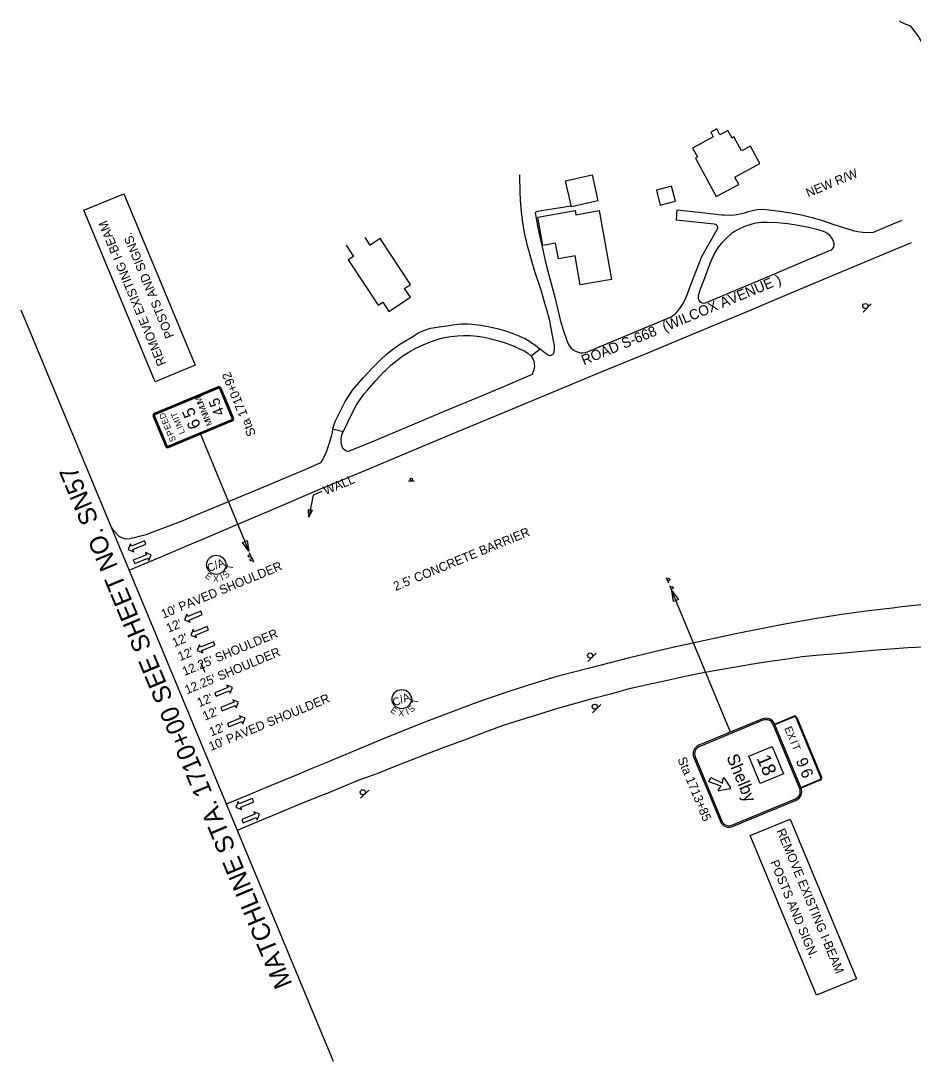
# Model space of a CAD drawing. Extents: x 1817507 to 1819117, y 1191678 to 1192982.
# Drawn here: x 1817507 to 1818204, y 1191678 to 1192491 of the extents above; entities that cross this region are included whole.
import ezdxf

# ---------------------------------------------------------------- set-up
doc = ezdxf.new("R2010")
doc.units = 0
for name, color, linetype in [('RD_EX_Bldg', 7, 'Continuous'), ('RD_EX_Road', 7, 'Continuous'), ('RD_HC_Data_Tic', 7, 'Continuous'), ('RD_PD_Final_LnLine', 7, 'Continuous'), ('RD_PD_Final_TX', 7, 'Continuous'), ('RD_PD_RW_TX', 7, 'Continuous'), ('RD_SHT_MatchLine', 7, 'Continuous'), ('RD_SHT_TX', 7, 'Continuous'), ('RD_Sketch8', 7, 'Continuous'), ('RD_TX_RoadID', 7, 'Continuous'), ('SN_P_Signs', 7, 'Continuous'), ('TERMINATOR', 7, 'Continuous')]:
    doc.layers.add(name, color=color, linetype=linetype)

# ---------------------------------------------------------------- blocks, each defined once
blk = doc.blocks.new('SARRW2')
at = {"layer": 'RD_PD_Final_LnLine'}
blk.add_lwpolyline([(-12, 1.2), (-12, -1.2), (-2.83, -1.2), (-2.83, -2.83), (0, 0), (-2.83, 2.83), (-2.83, 1.2)], close=True, dxfattribs=at)

msp = doc.modelspace()

# ---------------------------------------------------------------- linework, layer by layer
at = {"layer": 'RD_EX_Bldg'}
for points in [[(1818031.47, 1192391.37), (1818035.22, 1192384.42), (1818033.69, 1192383.6), (1818049.94, 1192353.45), (1818067.63, 1192362.98), (1818064.54, 1192368.72), (1818083.98, 1192379.2), (1818076.62, 1192392.85), (1818069.66, 1192389.1), (1818063.78, 1192400.02), (1818062.29, 1192399.22), (1818059.13, 1192405.06), (1818052.88, 1192401.69), (1818050.41, 1192406.26), (1818045.67, 1192403.7), (1818047.63, 1192400.08), (1818031.47, 1192391.37)], [(1817932.31, 1192365.67), (1817952.95, 1192370.38), (1817957.57, 1192350.16), (1817936.93, 1192345.45), (1817932.31, 1192365.67)], [(1818003.23, 1192358.55), (1818006.23, 1192346.88), (1818018.11, 1192349.93), (1818015.11, 1192361.6), (1818003.23, 1192358.55)], [(1817914.48, 1192315.22), (1817910.53, 1192337.34), (1817939.79, 1192342.58), (1817940.38, 1192339.28), (1817958.52, 1192342.52), (1817968.11, 1192288.87), (1817943.81, 1192284.53), (1817939.74, 1192307.29), (1817926.67, 1192304.95), (1817924.51, 1192317.01), (1817914.48, 1192315.22)], [(1817760.94, 1192315.48), (1817766.66, 1192306.82), (1817762.48, 1192304.05), (1817785.91, 1192268.6), (1817789.6, 1192271.04), (1817794.37, 1192263.81), (1817811.08, 1192274.85), (1817806.49, 1192281.79), (1817811.23, 1192284.92), (1817787.51, 1192320.81), (1817779.61, 1192315.58), (1817775.7, 1192321.49)]]:
    msp.add_lwpolyline(points, dxfattribs=at)
at = {"layer": 'RD_EX_Road'}
for points in [[(1818261.58, 1192366.73), (1818262.42, 1192368.15), (1818263.13, 1192369.69), (1818263.78, 1192371.95), (1818264.05, 1192374.28), (1818263.92, 1192376.63), (1818263.72, 1192377.76), (1818263.24, 1192380.13), (1818262.38, 1192382.4), (1818261.87, 1192383.37), (1818257.12, 1192392.2), (1818250.7, 1192404.08), (1818244.61, 1192414.31), (1818236, 1192429.02), (1818230.42, 1192439.59), (1818223.55, 1192452.27), (1818216.46, 1192464.6), (1818209.02, 1192476.73), (1818208.32, 1192477.83), (1818201.84, 1192486.47), (1818198.24, 1192487.72), (1818194.24, 1192489.73), (1818193.11, 1192490.73)], [(1817896.23, 1192370.43), (1817896.28, 1192369.33), (1817896.46, 1192357.47), (1817896.78, 1192350.57), (1817897.55, 1192341.7), (1817898.7, 1192332.87), (1817900.25, 1192324.1), (1817902.18, 1192315.4), (1817908.13, 1192295.38), (1817913.13, 1192279.94), (1817915.6, 1192271.29), (1817917.19, 1192266.04), (1817919.37, 1192257.72), (1817921.17, 1192249.31), (1817922.92, 1192239.6), (1817923.29, 1192237.51), (1817923.44, 1192234.75), (1817923.19, 1192231.99), (1817922.95, 1192231.12), (1817922.33, 1192230.2), (1817921.43, 1192229.55), (1817920.36, 1192229.25), (1817919.25, 1192229.35), (1817918.24, 1192229.82), (1817916.84, 1192230.92), (1817916.39, 1192231.3), (1817912.55, 1192234.38), (1817905.5, 1192228.81), (1817906.62, 1192227.09), (1817907.44, 1192225.12), (1817907.88, 1192223.03), (1817907.94, 1192220.9), (1817907.6, 1192218.8), (1817907.46, 1192218.33), (1817906.82, 1192216.07), (1817906.32, 1192214.46), (1817883.9, 1192205.01), (1817863.19, 1192196.39), (1817838, 1192185.86), (1817814.07, 1192175.86), (1817799.28, 1192169.66), (1817778.86, 1192161.04), (1817762.56, 1192154.46), (1817761.13, 1192154.8), (1817759.85, 1192155.52), (1817758.79, 1192156.54), (1817758.2, 1192157.48), (1817757.41, 1192159.97), (1817757, 1192162.55), (1817756.94, 1192163.92), (1817757.37, 1192166.53), (1817758.19, 1192169.05), (1817758.52, 1192169.78), (1817758.53, 1192169.81), (1817750.31, 1192171.98), (1817749.95, 1192169.61), (1817749.27, 1192166.3), (1817747.45, 1192160.14), (1817745.6, 1192154.79), (1817744.85, 1192152.82), (1817743.11, 1192149.09), (1817741.02, 1192145.54), (1817728.69, 1192140.25), (1817693.3, 1192125.42), (1817658.23, 1192110.83), (1817636.34, 1192101.67)], [(1817936.79, 1192346.06), (1817910.08, 1192341.77), (1817909.03, 1192341.34), (1817908.66, 1192340.74), (1817910.31, 1192330.69), (1817912.34, 1192320.71), (1817914.76, 1192310.81), (1817915.18, 1192309.25), (1817917.66, 1192298.06), (1817923.93, 1192274.91), (1817928.11, 1192257.27), (1817930.36, 1192249.53), (1817932.99, 1192241.91), (1817934.1, 1192239.03), (1817935.15, 1192237.1), (1817936.53, 1192235.39), (1817938.19, 1192233.95), (1817940.08, 1192232.83), (1817942.15, 1192232.07), (1817942.31, 1192232.03), (1817944.07, 1192231.52), (1817945.9, 1192231.41), (1817947.71, 1192231.69), (1817948.12, 1192231.81), (1817976.76, 1192243.75), (1818014.73, 1192259.52), (1818015.59, 1192260.09), (1818018.04, 1192262.16), (1818018.91, 1192263.07), (1818021.41, 1192266.06), (1818023.6, 1192269.29), (1818025.45, 1192272.72), (1818026.95, 1192276.32), (1818032.1, 1192290.13), (1818038.72, 1192306.82), (1818040.94, 1192310.77), (1818050.79, 1192327.78), (1818051.1, 1192328.46), (1818051.2, 1192329.49), (1818050.91, 1192330.48), (1818050.27, 1192331.29), (1818049.38, 1192331.8), (1818048.36, 1192331.95), (1818041, 1192332.7), (1818018.84, 1192334.98), (1818019.57, 1192343.07), (1818041.03, 1192340.88), (1818054.43, 1192339.29), (1818055.77, 1192339.16), (1818060.12, 1192339.03), (1818064.46, 1192339.29), (1818068.76, 1192339.94), (1818072.98, 1192340.97), (1818074.89, 1192341.72), (1818078.4, 1192342.75), (1818081.99, 1192343.4), (1818085.63, 1192343.66), (1818089.28, 1192343.53), (1818092.89, 1192343), (1818099.89, 1192342.23), (1818108.29, 1192340.93), (1818116.62, 1192339.25), (1818124.86, 1192337.19), (1818133, 1192334.74), (1818141.01, 1192331.92), (1818156.15, 1192327.21), (1818156.46, 1192327.12), (1818160.46, 1192326.18), (1818164.53, 1192325.63), (1818168.64, 1192325.47), (1818172.74, 1192325.7), (1818188.21, 1192332.29), (1818195.06, 1192335.13)], [(1818139.29, 1192311.67), (1818140.18, 1192312), (1818141, 1192312.85), (1818141.72, 1192314.11), (1818142.07, 1192315.52), (1818142.04, 1192316.97), (1818141.62, 1192318.36), (1818141.12, 1192319.61), (1818140.01, 1192321.51), (1818138.59, 1192323.19), (1818136.89, 1192324.59), (1818134.96, 1192325.66), (1818132.88, 1192326.38), (1818128.54, 1192327.71), (1818122.05, 1192329.36), (1818121.9, 1192329.4), (1818113.98, 1192330.95), (1818105.98, 1192332.12), (1818097.94, 1192332.9), (1818089.87, 1192333.28), (1818089.48, 1192333.29), (1818085.28, 1192333.16), (1818081.12, 1192332.63), (1818077.02, 1192331.71), (1818073.03, 1192330.41), (1818071.64, 1192329.92), (1818068.14, 1192328.4), (1818064.81, 1192326.52), (1818061.7, 1192324.31), (1818058.82, 1192321.79), (1818056.94, 1192320.03), (1818053.86, 1192316.73), (1818051.07, 1192313.17), (1818048.61, 1192309.38), (1818045.22, 1192301.7), (1818040.68, 1192289.88), (1818037.1, 1192280.33), (1818035.94, 1192275.95), (1818035.97, 1192273.84), (1818036.22, 1192272.94), (1818036.87, 1192271.85), (1818037.82, 1192271.01), (1818038.98, 1192270.5), (1818040.24, 1192270.37), (1818041.48, 1192270.63), (1818060.96, 1192278.7), (1818086.3, 1192289.39), (1818121.84, 1192304.39), (1818139.29, 1192311.67)], [(1817645.01, 1192084.41), (1817648.4, 1192085.86), (1817658.77, 1192090.29), (1817674.63, 1192096.91), (1817701.6, 1192108.51), (1817736.86, 1192123.57), (1817778.21, 1192140.68), (1817814.58, 1192155.92), (1817849.51, 1192170.5), (1817887.79, 1192186.58), (1817932.79, 1192205.24), (1817958.22, 1192215.86), (1817997.72, 1192232.05), (1818037.55, 1192248.7), (1818075.33, 1192264.29), (1818110.36, 1192279.19), (1818145.64, 1192293.97), (1818180.68, 1192308.65), (1818202.37, 1192317.6)], [(1817750.31, 1192171.98), (1817752.72, 1192178.32), (1817755.44, 1192184.17), (1817757.88, 1192188.72), (1817760.25, 1192193.43), (1817762.97, 1192197.95), (1817766.02, 1192202.26), (1817767.8, 1192204.49), (1817774.48, 1192212.31), (1817781.44, 1192219.86), (1817787.41, 1192225.9), (1817792.09, 1192230.14), (1817797.02, 1192234.07), (1817802.19, 1192237.69), (1817807.26, 1192240.79), (1817811.82, 1192243.51), (1817813.8, 1192244.8), (1817816.92, 1192246.8), (1817820.24, 1192248.46), (1817823.72, 1192249.76), (1817827.09, 1192250.63), (1817831.71, 1192251.43), (1817841.21, 1192252.87), (1817846, 1192253.66), (1817850.84, 1192254.06), (1817855.7, 1192254.07), (1817859.38, 1192253.81), (1817866.29, 1192252.99), (1817873.14, 1192251.78), (1817879.91, 1192250.19), (1817885.32, 1192248.62), (1817890.66, 1192246.92), (1817895.87, 1192244.84), (1817900.91, 1192242.41), (1817904.25, 1192240.55), (1817910.44, 1192236.08), (1817912.55, 1192234.38)], [(1817758.53, 1192169.81), (1817762.26, 1192177.37), (1817766.66, 1192186.39), (1817769.06, 1192190.88), (1817771.81, 1192195.17), (1817774.88, 1192199.24), (1817777.62, 1192202.38), (1817783.91, 1192209.62), (1817790.5, 1192216.6), (1817791.64, 1192217.75), (1817795.93, 1192221.83), (1817800.48, 1192225.62), (1817805.28, 1192229.09), (1817809.99, 1192232.06), (1817815.44, 1192235.12), (1817821.07, 1192237.84), (1817826.87, 1192240.19), (1817832.7, 1192242.15), (1817837.71, 1192243.44), (1817842.8, 1192244.34), (1817847.94, 1192244.85), (1817852.69, 1192244.97), (1817858.04, 1192244.91), (1817863.38, 1192244.45), (1817868.67, 1192243.61), (1817873.88, 1192242.38), (1817874.45, 1192242.22), (1817880.25, 1192240.84), (1817885.94, 1192239.09), (1817891.5, 1192236.97), (1817896.92, 1192234.48), (1817897.02, 1192234.43), (1817900.01, 1192232.94), (1817902.79, 1192231.12), (1817905.5, 1192228.81)], [(1817636.34, 1192101.67), (1817633.34, 1192100.42), (1817605.7, 1192089.83)], [(1817577.66, 1192094.8), (1817578.53, 1192093.71), (1817583.41, 1192088.25), (1817585.41, 1192087.23), (1817587.55, 1192086.57), (1817589.78, 1192086.3), (1817592.02, 1192086.42), (1817594.2, 1192086.93), (1817594.72, 1192087.11), (1817600.51, 1192088.51), (1817605.7, 1192089.83)], [(1817591.4, 1192061.72), (1817599.97, 1192065.4), (1817618.26, 1192073.01), (1817633.33, 1192079.43), (1817645.01, 1192084.41)], [(1818214.62, 1192035.23), (1818192.87, 1192032.88), (1818187.62, 1192032.26), (1818166.84, 1192029.75), (1818146.11, 1192026.86), (1818125.44, 1192023.58), (1818104.84, 1192019.9), (1818096.74, 1192018.35), (1818065.31, 1192012.08), (1818033.97, 1192005.43), (1818013.74, 1192000.92), (1817982.27, 1191993.35), (1817950.9, 1191985.4), (1817925.55, 1191978.67), (1817907.52, 1191973.39), (1817889.61, 1191967.72), (1817871.81, 1191961.69), (1817860.95, 1191957.8), (1817838.7, 1191949.51), (1817820.42, 1191942.39), (1817789.45, 1191929.77), (1817743.27, 1191910.63), (1817734.2, 1191906.85)], [(1817744.22, 1191886.93), (1817753.55, 1191890.71), (1817771.02, 1191898.04), (1817785.23, 1191902.96), (1817799.2, 1191908.67), (1817813.22, 1191914.27), (1817827.35, 1191919.66), (1817841.22, 1191924.95), (1817855.35, 1191930.19), (1817869.68, 1191935.48), (1817883.86, 1191940.77), (1817897.94, 1191945.19), (1817912.11, 1191949.66), (1817926.34, 1191954.08), (1817940.27, 1191957.98), (1817954.24, 1191961.89), (1817968.31, 1191965.64), (1817982.24, 1191969.34), (1817996.05, 1191972.52), (1818009.62, 1191975.5), (1818023.33, 1191978.58), (1818036.95, 1191981.31), (1818049.89, 1191983.77), (1818063.61, 1191986.13), (1818077.07, 1191988.34), (1818089.91, 1191990.6), (1818103.52, 1191992.45), (1818116.98, 1191994.3), (1818130.7, 1191995.64), (1818144.42, 1191996.87), (1818158.23, 1191998.16), (1818172.16, 1191999.23), (1818185.77, 1192000.42), (1818199.49, 1192001.44), (1818212.84, 1192002.06)], [(1817734.2, 1191906.85), (1817722.75, 1191902.08), (1817697.85, 1191891.9), (1817683.04, 1191885.66), (1817667.28, 1191879.14)], [(1817744.22, 1191886.93), (1817738.67, 1191884.67), (1817724.73, 1191879), (1817711.35, 1191873.31), (1817692.91, 1191865.73), (1817675.81, 1191858.62)]]:
    msp.add_lwpolyline(points, dxfattribs=at)
at = {"layer": 'RD_HC_Data_Tic'}
msp.add_line((1817650.9, 1191981.81), (1817647.83, 1191989.2), dxfattribs=at)
at = {"layer": 'RD_PD_Final_TX'}
for p, q in [((1817735.14, 1192120.35), (1817731.88, 1192103.11)), ((1817742.02, 1192123.21), (1817735.14, 1192120.35))]:
    msp.add_line(p, q, dxfattribs=at)
at = {"layer": 'RD_SHT_MatchLine'}
msp.add_line((1817506.85, 1192265.17), (1817750.69, 1191678.44), dxfattribs=at)
at = {"layer": 'RD_Sketch8'}
for centre in [(1817659.5, 1192066), (1817804.29, 1191961.12)]:
    msp.add_circle(centre, 7.5, dxfattribs=at)
at = {"layer": 'SN_P_Signs'}
for p, q in [((1817556.2, 1192342.81), (1817587.24, 1192355.71)), ((1817587.24, 1192355.71), (1817642.9, 1192221.79)), ((1817611.85, 1192208.89), (1817556.2, 1192342.81)), ((1818164.65, 1192263.37), (1818171.01, 1192269.73)), ((1817642.9, 1192221.79), (1817611.85, 1192208.89)), ((1817660.95, 1192204.92), (1817611.08, 1192184.19)), ((1817672.97, 1192180.68), (1817663.3, 1192203.95)), ((1817610.11, 1192181.84), (1817619.78, 1192158.57)), ((1817622.13, 1192157.6), (1817672, 1192178.32)), ((1817647.07, 1192167.96), (1817684.98, 1192076.74)), ((1817809.6, 1192131.67), (1817814.1, 1192131.67)), ((1817687.18, 1192071.18), (1817685.45, 1192075.34)), ((1817688.79, 1192068.15), (1817687.06, 1192072.3)), ((1818010.82, 1192056.14), (1818012.57, 1192051.99)), ((1818013.57, 1192049.8), (1818015.32, 1192045.66)), ((1818061.15, 1191935.38), (1818015.32, 1192045.66)), ((1817949.77, 1191990.53), (1817956.13, 1191996.89)), ((1817953.35, 1191950.54), (1817959.72, 1191956.9)), ((1818086.47, 1191944.6), (1818036.75, 1191923.94)), ((1818075.48, 1191916.62), (1818093.66, 1191924.17)), ((1818084.33, 1191895.31), (1818075.48, 1191916.62)), ((1818102.52, 1191902.87), (1818084.33, 1191895.31)), ((1817772.19, 1191883.81), (1817778.56, 1191890.17)), ((1818062.2, 1191862.7), (1818111.92, 1191883.36)), ((1818076.53, 1191854.55), (1818107.58, 1191867.45)), ((1818107.58, 1191867.45), (1818159.39, 1191742.77)), ((1818128.35, 1191729.87), (1818076.53, 1191854.55)), ((1818159.39, 1191742.77), (1818128.35, 1191729.87))]:
    msp.add_line(p, q, dxfattribs=at)
for points in [[(1817661.12, 1192204.5), (1817611.25, 1192183.78)], [(1817661.41, 1192203.81), (1817611.54, 1192183.09)], [(1817671.86, 1192180.21), (1817662.19, 1192203.49)], [(1817672.55, 1192180.5), (1817662.88, 1192203.77)], [(1817610.53, 1192182.01), (1817620.2, 1192158.74)], [(1817611.22, 1192182.3), (1817620.89, 1192159.03)], [(1817621.67, 1192158.71), (1817671.54, 1192179.43)], [(1817621.96, 1192158.01), (1817671.83, 1192178.74)], [(1818086, 1191945.71), (1818036.29, 1191925.05)], [(1818115.15, 1191891.2), (1818094.31, 1191941.36)], [(1818116.26, 1191891.66), (1818095.42, 1191941.82)], [(1818110.73, 1191947.19), (1818095.77, 1191940.97), (1818095.54, 1191941.53), (1818110.5, 1191947.74)], [(1818131.64, 1191900), (1818112.3, 1191946.54)], [(1818112.85, 1191946.77), (1818132.19, 1191900.23)], [(1818093.66, 1191924.17), (1818102.52, 1191902.87)], [(1818032.4, 1191915.64), (1818053.25, 1191865.48)], [(1818033.51, 1191916.1), (1818054.36, 1191865.94)], [(1818044.26, 1191896.49), (1818045.63, 1191899.82), (1818054.75, 1191895.57)], [(1818053.72, 1191893.07), (1818044.26, 1191896.49)], [(1818051.54, 1191890.11), (1818053.72, 1191893.07)], [(1818054.75, 1191895.57), (1818055.29, 1191899.2)], [(1818056.11, 1191899.39), (1818061.13, 1191891.88)], [(1818116.03, 1191892.22), (1818130.99, 1191898.43)], [(1818131.22, 1191897.88), (1818116.26, 1191891.66), (1818116.03, 1191892.22)], [(1818060.84, 1191891.19), (1818051.99, 1191889.41)], [(1818062.66, 1191861.59), (1818112.38, 1191882.25)]]:
    msp.add_lwpolyline(points, dxfattribs=at)
for points in [[(1817683.72, 1192085.1), (1817684.98, 1192076.74), (1817679.93, 1192083.53)], [(1818016.71, 1192037.32), (1818015.36, 1192045.67), (1818020.48, 1192038.94)]]:
    msp.add_lwpolyline(points, close=True, dxfattribs=at)
for centre, radius in [((1818166.41, 1192267.99), 2), ((1817811.85, 1192132.68), 1), ((1817685.38, 1192072.88), 1), ((1817686.98, 1192069.84), 1), ((1818012.63, 1192054.45), 1), ((1818015.38, 1192048.11), 1), ((1817951.53, 1191995.15), 2), ((1817955.12, 1191955.16), 2), ((1817773.96, 1191888.43), 2)]:
    msp.add_circle(centre, radius, dxfattribs=at)
for centre, radius, start, end in [((1817661.64, 1192203.25), 1.8, 22.56659, 112.56659), ((1817661.64, 1192203.25), 1.35, 22.56659, 112.56659), ((1817661.64, 1192203.25), 0.6, 22.56659, 112.56659), ((1817611.77, 1192182.53), 1.8, 112.56659, 202.56659), ((1817611.77, 1192182.53), 1.35, 112.56659, 202.56659), ((1817611.77, 1192182.53), 0.6, 112.56659, 202.56659), ((1817671.31, 1192179.98), 0.6, 292.56659, 22.56659), ((1817671.31, 1192179.98), 1.35, 292.56659, 22.56659), ((1817671.31, 1192179.98), 1.8, 292.56659, 22.56659), ((1817621.44, 1192159.26), 1.8, 202.56659, 292.56659), ((1817621.44, 1192159.26), 1.35, 202.56659, 292.56659), ((1817621.44, 1192159.26), 0.6, 202.56659, 292.56659), ((1818088.77, 1191939.06), 7.2, 22.56659, 112.56659), ((1818088.77, 1191939.06), 6, 22.56659, 112.56659), ((1818111.19, 1191946.08), 1.8, 22.56659, 112.56659), ((1818111.19, 1191946.08), 1.2, 22.56659, 112.56659), ((1818039.05, 1191918.4), 7.2, 112.56659, 202.56659), ((1818039.05, 1191918.4), 6, 112.56659, 202.56659), ((1818055.74, 1191899.14), 0.45, 33.74449, 171.52869), ((1818130.53, 1191899.54), 1.2, 292.56659, 22.56659), ((1818130.53, 1191899.54), 1.8, 292.56659, 22.56659), ((1818051.9, 1191889.85), 0.45, 143.60449, 281.38869), ((1818060.75, 1191891.63), 0.45, 281.38869, 33.74449), ((1818109.61, 1191888.9), 6, 292.56659, 22.56659), ((1818109.61, 1191888.9), 7.2, 292.56659, 22.56659), ((1818059.9, 1191868.24), 7.2, 202.56659, 292.56659), ((1818059.9, 1191868.24), 6, 202.56659, 292.56659)]:
    msp.add_arc(centre, radius, start, end, dxfattribs=at)
at = {"layer": 'TERMINATOR'}
msp.add_lwpolyline([(1817734.47, 1192108.73), (1817731.88, 1192103.11), (1817731.52, 1192109.28)], close=True, dxfattribs=at)

# ---------------------------------------------------------------- block references
at = {"layer": 'RD_PD_Final_LnLine', "xscale": 1.2000000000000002}
for p, yscale, rotation in [((1817590.6, 1192077.9), 1.2000000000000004, -157.44760385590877), ((1817608.58, 1192073.79), 1.2000000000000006, 22.552396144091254), ((1817634.69, 1192022.92), 1.2000000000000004, -157.44760385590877), ((1817639.65, 1192010.98), 1.2000000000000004, -157.44760385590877), ((1817644.61, 1191999.04), 1.2000000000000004, -157.44760385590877), ((1817672.18, 1191970.22), 1.2000000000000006, 22.552396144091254), ((1817676.93, 1191958.79), 1.2000000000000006, 22.552396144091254), ((1817682.15, 1191946.23), 1.2000000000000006, 22.552396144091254), ((1817674.9, 1191876.7), 1.2000000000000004, -157.44760385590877), ((1817693.29, 1191871.27), 1.2000000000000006, 22.552396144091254)]:
    msp.add_blockref('SARRW2', p, dxfattribs=dict(at, yscale=yscale, rotation=rotation))

# ---------------------------------------------------------------- texts
at = {"layer": 'RD_PD_Final_TX'}
for s, rotation, p in [('WALL', 22.56659, (1817744.91, 1192120.38)), ("2.5' CONCRETE BARRIER", 22.4268, (1817799.55, 1192045.52)), ("10' PAVED SHOULDER", 22.4268, (1817618.21, 1192023.91)), ("12'", 22.75903, (1817622.11, 1192012.82)), ("12.25' SHOULDER", 22.56659, (1817634.72, 1191979.16)), ("12'", 22.75903, (1817626.76, 1192001.63)), ("12'", 22.75903, (1817631.29, 1191990.73)), ("12.25' SHOULDER", 22.56659, (1817636.58, 1191964.77)), ("12'", 22.75903, (1817646.25, 1191954.73)), ("10' PAVED SHOULDER", 22.4268, (1817655.34, 1191920.6)), ("12'", 22.75903, (1817650.6, 1191944.26)), ("12'", 22.75903, (1817655.75, 1191931.88))]:
    msp.add_text(s, height=7, rotation=rotation, dxfattribs=at).set_placement(p)
at = {"layer": 'RD_PD_RW_TX'}
msp.add_text('NEW R/W', height=7, rotation=22.56659, dxfattribs=at).set_placement((1818121.79, 1192352.76))
at = {"layer": 'RD_SHT_TX'}
msp.add_text('MATCHLINE STA. 1710+00 SEE SHEET NO. SN57', height=14.1726, rotation=112.67894, dxfattribs=at).set_placement((1817719.09, 1191738.69))
at = {"layer": 'RD_Sketch8'}
for s, height, rotation, p in [('C/A', 6.25, 22.56659, (1817653.92, 1192060.12)), ('T', 5, 80.75173, (1817672.26, 1192061.86)), ('E', 5, 325.77783, (1817650.34, 1192056.21)), ('X', 5, 358.2072, (1817656.92, 1192052.82)), ('I', 5, 22.3672, (1817663.98, 1192053.51)), ('S', 5, 44.35903, (1817667.28, 1192055.07)), ('C/A', 6.25, 22.56659, (1817798.7, 1191955.25)), ('T', 5, 80.75173, (1817817.04, 1191956.99)), ('E', 5, 325.77783, (1817795.12, 1191951.33)), ('X', 5, 358.2072, (1817801.7, 1191947.94)), ('I', 5, 22.3672, (1817808.76, 1191948.63)), ('S', 5, 44.35903, (1817812.07, 1191950.19))]:
    msp.add_text(s, height=height, rotation=rotation, dxfattribs=at).set_placement(p)
at = {"layer": 'RD_TX_RoadID'}
msp.add_text('ROAD S-668  (WILCOX AVENUE )', height=8, rotation=22.49043, dxfattribs=at).set_placement((1817946.63, 1192221.64))
at = {"layer": 'SN_P_Signs'}
for s, height, rotation, p in [('REMOVE EXISTING I-BEAM', 6.9998, 112.56667, (1817620.45, 1192223.02)), ('POSTS AND SIGNS.', 6.9998, 112.56667, (1817626.69, 1192244.5)), ('Sta 1710+92', 7, 112.56667, (1817690.61, 1192167.99)), ('M', 4.8, 112.56659, (1817649.32, 1192193.03)), ('U', 4.8, 112.56659, (1817650.71, 1192189.68)), ('5', 8.4, 112.56659, (1817663.3, 1192191.44)), ('5', 9.6, 112.56659, (1817643.99, 1192183.18)), ('M', 4.8, 112.56659, (1817652.29, 1192185.87)), ('I', 4.8, 112.56659, (1817652.94, 1192184.31)), ('4', 8.4, 112.56659, (1817666.27, 1192184.29)), ('D', 4.8, 112.56659, (1817620.84, 1192181.03)), ('E', 4.8, 112.56659, (1817622.59, 1192176.83)), ('T', 4.8, 112.56659, (1817629.82, 1192182.09)), ('I', 4.8, 112.56659, (1817630.52, 1192180.41)), ('M', 4.8, 112.56659, (1817632.69, 1192175.19)), ('6', 9.6, 112.56659, (1817647.68, 1192174.29)), ('N', 4.8, 112.56659, (1817654.34, 1192180.95)), ('I', 4.8, 112.56659, (1817654.98, 1192179.4)), ('M', 4.8, 112.56659, (1817656.57, 1192175.59)), ('E', 4.8, 112.56659, (1817624.33, 1192172.64)), ('P', 4.8, 112.56659, (1817626.29, 1192167.93)), ('I', 4.8, 112.56659, (1817633.48, 1192173.28)), ('L', 4.8, 112.56659, (1817635.22, 1192169.11)), ('S', 4.8, 112.56659, (1817628.24, 1192163.22)), ('E', 6, 292.56659, (1818103, 1191938.42)), ('X', 6, 292.56659, (1818104.98, 1191933.66)), ('I', 6, 292.56659, (1818107.59, 1191927.37)), ('T', 6, 292.56659, (1818108.74, 1191924.62)), ('Shelby', 9.6, 292.56659, (1818057.76, 1191915.94)), ('18', 10.8, 292.56659, (1818081.37, 1191915.05)), ('Sta 1713+85', 7, 292.56667, (1818019.59, 1191914.24)), ('9', 9, 292.56659, (1818111.91, 1191913.08)), ('6', 9, 292.56659, (1818115.4, 1191904.67)), ('REMOVE EXISTING I-BEAM', 6.9998, 292.56667, (1818096.88, 1191858.36)), ('POSTS AND SIGN.', 6.9998, 292.56667, (1818091.9, 1191833.87))]:
    msp.add_text(s, height=height, rotation=rotation, dxfattribs=at).set_placement(p)

doc.saveas('drawing.dxf')
